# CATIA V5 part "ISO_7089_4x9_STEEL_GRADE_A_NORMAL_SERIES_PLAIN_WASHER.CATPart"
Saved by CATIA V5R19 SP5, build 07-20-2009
Part number: ISO 7089 WASHER 4x9 STEEL GRADE A PLAIN NORMAL SERIES
Publications: "Mating Face", "Axis"
Bounding box of the stored display mesh (mm): x 0 to 0.8, y -4.5 to 4.5, z -4.5 to 4.5
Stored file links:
  Z:\UA\ATLAS\atlascar\ServoPiloto\dir\suportePotenciometro\potenciometro\ISO_7089_4x9_STEEL_GRADE_A_NORMAL_SERIES_PLAIN_WASHER.CATPart
  Z:\programs_vbox\Dassault Systemes\B19\intel_a\startup\components\MechanicalStandardParts\ISO_Standards\Design_Tables\ISO_7089_PLAIN_WASHER_GRADE_A_NORMAL_SERIES.txt
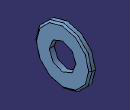
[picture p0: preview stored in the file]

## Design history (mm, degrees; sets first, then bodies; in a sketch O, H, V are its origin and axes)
Parameters
  d1_inside_dia = 4.3 mm
  d2_outside_dia = 9 mm
  h_thick = 0.8 mm
  Nominal_dia = 4 mm
Body1 "PartBody" (main body)
  Sketch1 on yz-plane, origin (0, 0, 0), H (0, 1, 0), V (0, 0, 1)
    circle A1 centre (0, 0) radius 4.5
    circle A2 centre (0, 0) radius 2.15
    radius A1 = 4.5 {= d2_outside_dia /2}
    radius A2 = 2.15 {= d1_inside_dia /2}
  Pad1: profile Sketch1, direction (1, 0, 0), length 0.8 {= h_thick}
  Chamfer1: length 0.3 {= 0.375*h_thick}, angle 37.5, on edge [face of Pad1 | face of Pad1]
